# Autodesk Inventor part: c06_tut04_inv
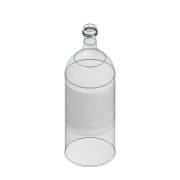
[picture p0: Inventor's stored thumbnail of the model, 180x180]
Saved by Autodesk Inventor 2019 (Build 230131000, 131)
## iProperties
Created: 2015-03
Part Number: c06_tut04_inv
Material: Glass
Document SubType Name: Modeling
Designer: Sandeep
Density: 2.18 g/cm^3
Appearance: Clear
Author: Sandeep
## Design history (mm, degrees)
sketch "Sketch1"
  geometry: L1 (8, 180)-(8, 160); L2 (30, 113.567)-(30, 0); L3 (30, 0)-(0, 0); L4 (0, 0)-(0, -98.027); L5 (7, 180)-(7, 160); L6 (29, 113.567)-(29, 1); L7 (29, 1)-(0, 1); L8 (8, 180)-(7, 180); L9 (0, 1)-(0, 0); A1 r 30 centre (38, 160) between (8, 160) and (19, 136.784); A2 r 30 centre (0, 113.567) between (30, 113.567) and (19, 136.784); A3 r 31 centre (38, 160) between (7, 160) and (18.367, 136.01); A4 r 29 centre (0, 113.567) between (29, 113.567) and (18.367, 136.01)
  constraints: 18 end point, 8 point on circle, 4 centre point, 3 perpendicular, 3 tangent, 2 parallel, 2 vertical, 1 horizontal, 4 other
  dimensions: "d0" = 20 distance of L1.start L1.end; "d1" = 30 radius of A1; "d2" = 30 radius of A2; "d7" = 180 vertical distance of L3.end L1.start; "d17" = 1 distance between parallel lines of L5 L1; "d18" = 60 diameter of L2 L4; "d19" = 16 diameter of L1 L4
revolve "Revolution1" sketch "Sketch1" stored, may be unused: angle "d9" = 90 deg
workplane "Work Plane1"
sketch "Sketch2"
  geometry: L1 (-21.117, 118.431)-(137.947, 118.431); L2 (137.947, 118.431)-(137.947, 105.984); L3 (137.947, 105.984)-(-21.117, 105.984); L4 (-21.117, 105.984)-(-21.117, 118.431); 1 further point
  constraints: 2 other
emboss "Emboss1" sketch "Sketch2" dims "d1" = 30, "d10" = 1, "d11" = 0
sketch "Sketch3"
  geometry: L1 (-60.338, 49.443)-(58.204, 49.443); L2 (58.204, 49.443)-(58.204, -13.263); L3 (58.204, -13.263)-(-60.338, -13.263); L4 (-60.338, -13.263)-(-60.338, 49.443); 1 further point; 1 other entity
  constraints: 2 other
feature "Decal1" sketch "Sketch3"
body "Solid1"
node "Image1"
